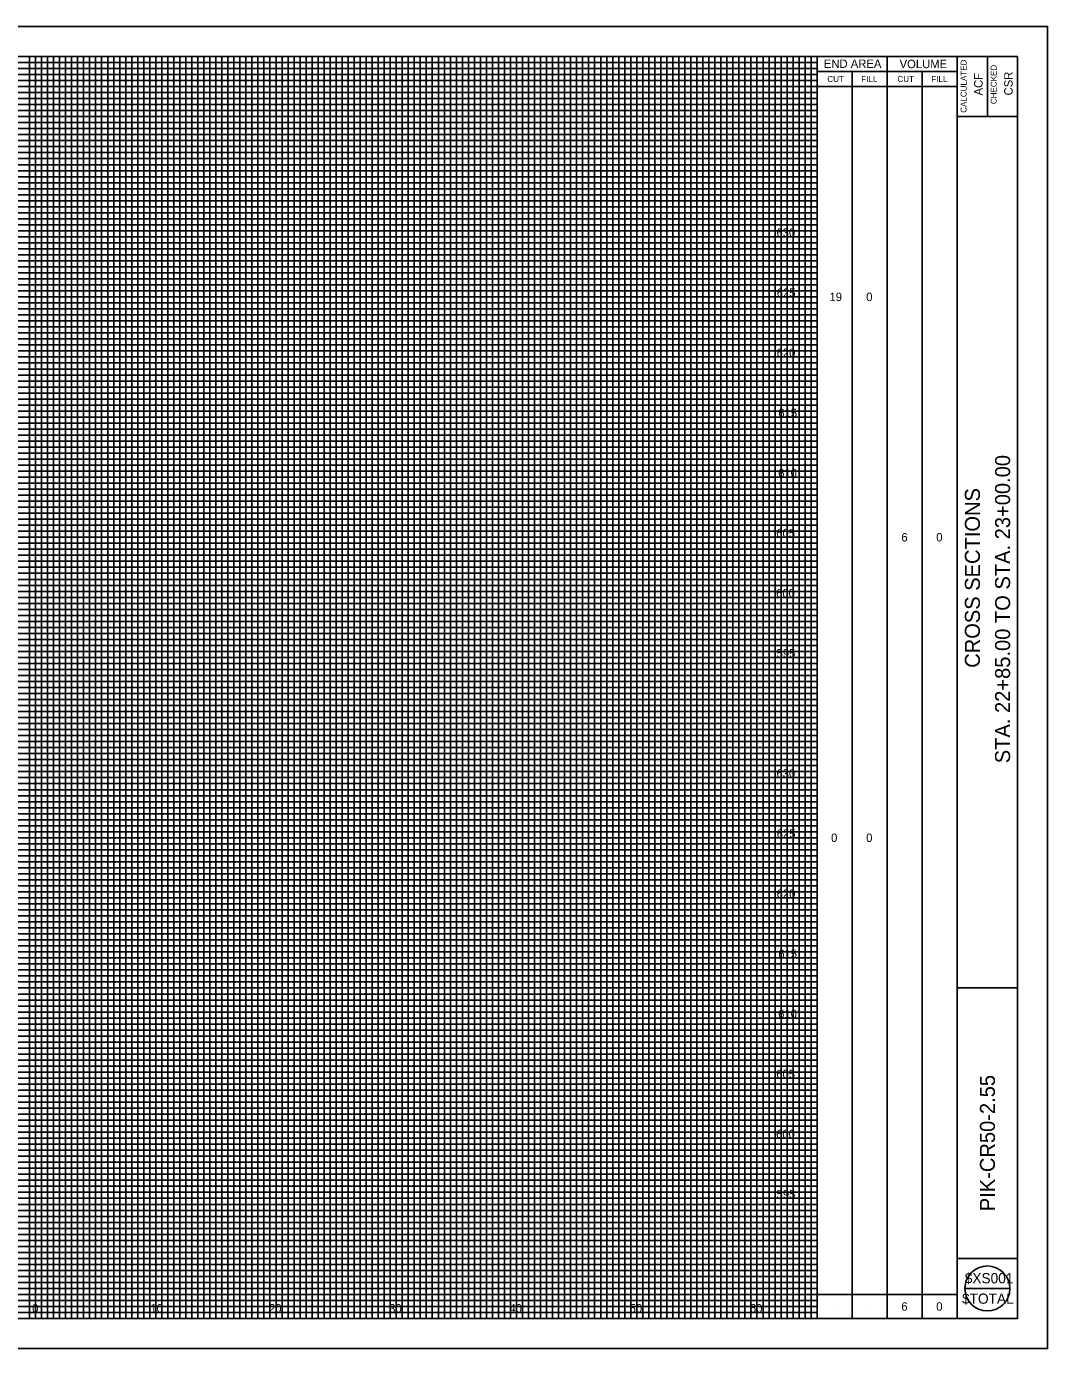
# Model space of a CAD drawing. Extents: x 1858928 to 1859278, y 421672 to 422012.
# Drawn here: x 1859012.6 to 1859097.5, y 421671.6 to 421781.6 of the extents above; entities that cross this region are included whole.
import ezdxf

# ---------------------------------------------------------------- set-up
doc = ezdxf.new("R2010")
doc.units = 0
for name, color, linetype in [('SH_Border', 7, 'Continuous'), ('SH_Cut_Line', 7, 'Continuous'), ('SH_Data', 7, 'Continuous'), ('SH_Major_Grid_Line', 7, 'Continuous'), ('SH_Minor_Grid_Line', 7, 'Continuous'), ('SH_Text', 7, 'Continuous')]:
    doc.layers.add(name, color=color, linetype=linetype)

msp = doc.modelspace()

# ---------------------------------------------------------------- linework, layer by layer
at = {"layer": 'SH_Border'}
for p, q in [((1859090.03, 421674.11), (1859090.03, 421779.11)), ((1859092.53, 421779.11), (1859092.53, 421774.11)), ((1859090.03, 421774.11), (1859095.03, 421774.11)), ((1859090.03, 421701.61), (1859095.03, 421701.61)), ((1859090.03, 421679.11), (1859095.03, 421679.11))]:
    msp.add_line(p, q, dxfattribs=at)
msp.add_lwpolyline([(1858937.53, 421779.11), (1859095.03, 421779.11), (1859095.03, 421674.11), (1858937.53, 421674.11)], close=True, dxfattribs=at)
at = {"layer": 'SH_Cut_Line'}
msp.add_lwpolyline([(1858927.53, 421671.61), (1859097.53, 421671.61), (1859097.53, 421781.61), (1858927.53, 421781.61)], close=True, dxfattribs=at)
at = {"layer": 'SH_Data'}
for p, q in [((1859078.37, 421674.11), (1859078.37, 421779.11)), ((1859084.2, 421674.11), (1859084.2, 421779.11)), ((1859078.37, 421777.86), (1859090.03, 421777.86)), ((1859081.28, 421674.11), (1859081.28, 421777.86)), ((1859087.12, 421674.11), (1859087.12, 421777.86)), ((1859078.37, 421776.61), (1859090.03, 421776.61)), ((1859090.66, 421676.61), (1859094.41, 421676.61)), ((1859078.37, 421676.11), (1859090.03, 421676.11)), ((1859079.83, 421675.11), (1859079.83, 421675.11)), ((1859082.74, 421675.11), (1859082.74, 421675.11)), ((1859085.66, 421675.11), (1859085.66, 421675.11)), ((1859088.58, 421675.11), (1859088.58, 421675.11))]:
    msp.add_line(p, q, dxfattribs=at)
msp.add_circle((1859092.53, 421676.61), 1.87, dxfattribs=at)
at = {"layer": 'SH_Major_Grid_Line'}
for p, q in [((1859013.37, 421674.11), (1859013.37, 421779.11)), ((1859018.37, 421674.11), (1859018.37, 421779.11)), ((1859023.37, 421674.11), (1859023.37, 421779.11)), ((1859028.37, 421674.11), (1859028.37, 421779.11)), ((1859033.37, 421674.11), (1859033.37, 421779.11)), ((1859038.37, 421674.11), (1859038.37, 421779.11)), ((1859043.37, 421674.11), (1859043.37, 421779.11)), ((1859048.37, 421674.11), (1859048.37, 421779.11)), ((1859053.37, 421674.11), (1859053.37, 421779.11)), ((1859058.37, 421674.11), (1859058.37, 421779.11)), ((1859063.37, 421674.11), (1859063.37, 421779.11)), ((1859068.37, 421674.11), (1859068.37, 421779.11)), ((1859073.37, 421674.11), (1859073.37, 421779.11)), ((1858943.37, 421774.11), (1859078.37, 421774.11)), ((1858943.37, 421769.11), (1859078.37, 421769.11)), ((1858943.37, 421764.11), (1859078.37, 421764.11)), ((1858943.37, 421759.11), (1859078.37, 421759.11)), ((1858943.37, 421754.11), (1859078.37, 421754.11)), ((1858943.37, 421749.11), (1859078.37, 421749.11)), ((1858943.37, 421744.11), (1859078.37, 421744.11)), ((1858943.37, 421739.11), (1859078.37, 421739.11)), ((1858943.37, 421734.11), (1859078.37, 421734.11)), ((1858943.37, 421729.11), (1859078.37, 421729.11)), ((1858943.37, 421724.11), (1859078.37, 421724.11)), ((1858943.37, 421719.11), (1859078.37, 421719.11)), ((1858943.37, 421714.11), (1859078.37, 421714.11)), ((1858943.37, 421709.11), (1859078.37, 421709.11)), ((1858943.37, 421704.11), (1859078.37, 421704.11)), ((1858943.37, 421699.11), (1859078.37, 421699.11)), ((1858943.37, 421694.11), (1859078.37, 421694.11)), ((1858943.37, 421689.11), (1859078.37, 421689.11)), ((1858943.37, 421684.11), (1859078.37, 421684.11)), ((1858943.37, 421679.11), (1859078.37, 421679.11))]:
    msp.add_line(p, q, dxfattribs=at)
at = {"layer": 'SH_Minor_Grid_Line'}
for p, q in [((1858943.37, 421778.61), (1859078.37, 421778.61)), ((1859012.87, 421674.11), (1859012.87, 421779.11)), ((1859013.87, 421674.11), (1859013.87, 421779.11)), ((1859014.37, 421674.11), (1859014.37, 421779.11)), ((1859014.87, 421674.11), (1859014.87, 421779.11)), ((1859015.37, 421674.11), (1859015.37, 421779.11)), ((1859015.87, 421674.11), (1859015.87, 421779.11)), ((1859016.37, 421674.11), (1859016.37, 421779.11)), ((1859016.87, 421674.11), (1859016.87, 421779.11)), ((1859017.37, 421674.11), (1859017.37, 421779.11)), ((1859017.87, 421674.11), (1859017.87, 421779.11)), ((1859018.87, 421674.11), (1859018.87, 421779.11)), ((1859019.37, 421674.11), (1859019.37, 421779.11)), ((1859019.87, 421674.11), (1859019.87, 421779.11)), ((1859020.37, 421674.11), (1859020.37, 421779.11)), ((1859020.87, 421674.11), (1859020.87, 421779.11)), ((1859021.37, 421674.11), (1859021.37, 421779.11)), ((1859021.87, 421674.11), (1859021.87, 421779.11)), ((1859022.37, 421674.11), (1859022.37, 421779.11)), ((1859022.87, 421674.11), (1859022.87, 421779.11)), ((1859023.87, 421674.11), (1859023.87, 421779.11)), ((1859024.37, 421674.11), (1859024.37, 421779.11)), ((1859024.87, 421674.11), (1859024.87, 421779.11)), ((1859025.37, 421674.11), (1859025.37, 421779.11)), ((1859025.87, 421674.11), (1859025.87, 421779.11)), ((1859026.37, 421674.11), (1859026.37, 421779.11)), ((1859026.87, 421674.11), (1859026.87, 421779.11)), ((1859027.37, 421674.11), (1859027.37, 421779.11)), ((1859027.87, 421674.11), (1859027.87, 421779.11)), ((1859028.87, 421674.11), (1859028.87, 421779.11)), ((1859029.37, 421674.11), (1859029.37, 421779.11)), ((1859029.87, 421674.11), (1859029.87, 421779.11)), ((1859030.37, 421674.11), (1859030.37, 421779.11)), ((1859030.87, 421674.11), (1859030.87, 421779.11)), ((1859031.37, 421674.11), (1859031.37, 421779.11)), ((1859031.87, 421674.11), (1859031.87, 421779.11)), ((1859032.37, 421674.11), (1859032.37, 421779.11)), ((1859032.87, 421674.11), (1859032.87, 421779.11)), ((1859033.87, 421674.11), (1859033.87, 421779.11)), ((1859034.37, 421674.11), (1859034.37, 421779.11)), ((1859034.87, 421674.11), (1859034.87, 421779.11)), ((1859035.37, 421674.11), (1859035.37, 421779.11)), ((1859035.87, 421674.11), (1859035.87, 421779.11)), ((1859036.37, 421674.11), (1859036.37, 421779.11)), ((1859036.87, 421674.11), (1859036.87, 421779.11)), ((1859037.37, 421674.11), (1859037.37, 421779.11)), ((1859037.87, 421674.11), (1859037.87, 421779.11)), ((1859038.87, 421674.11), (1859038.87, 421779.11)), ((1859039.37, 421674.11), (1859039.37, 421779.11)), ((1859039.87, 421674.11), (1859039.87, 421779.11)), ((1859040.37, 421674.11), (1859040.37, 421779.11)), ((1859040.87, 421674.11), (1859040.87, 421779.11)), ((1859041.37, 421674.11), (1859041.37, 421779.11)), ((1859041.87, 421674.11), (1859041.87, 421779.11)), ((1859042.37, 421674.11), (1859042.37, 421779.11)), ((1859042.87, 421674.11), (1859042.87, 421779.11)), ((1859043.87, 421674.11), (1859043.87, 421779.11)), ((1859044.37, 421674.11), (1859044.37, 421779.11)), ((1859044.87, 421674.11), (1859044.87, 421779.11)), ((1859045.37, 421674.11), (1859045.37, 421779.11)), ((1859045.87, 421674.11), (1859045.87, 421779.11)), ((1859046.37, 421674.11), (1859046.37, 421779.11)), ((1859046.87, 421674.11), (1859046.87, 421779.11)), ((1859047.37, 421674.11), (1859047.37, 421779.11)), ((1859047.87, 421674.11), (1859047.87, 421779.11)), ((1859048.87, 421674.11), (1859048.87, 421779.11)), ((1859049.37, 421674.11), (1859049.37, 421779.11)), ((1859049.87, 421674.11), (1859049.87, 421779.11)), ((1859050.37, 421674.11), (1859050.37, 421779.11)), ((1859050.87, 421674.11), (1859050.87, 421779.11)), ((1859051.37, 421674.11), (1859051.37, 421779.11)), ((1859051.87, 421674.11), (1859051.87, 421779.11)), ((1859052.37, 421674.11), (1859052.37, 421779.11)), ((1859052.87, 421674.11), (1859052.87, 421779.11)), ((1859053.87, 421674.11), (1859053.87, 421779.11)), ((1859054.37, 421674.11), (1859054.37, 421779.11)), ((1859054.87, 421674.11), (1859054.87, 421779.11)), ((1859055.37, 421674.11), (1859055.37, 421779.11)), ((1859055.87, 421674.11), (1859055.87, 421779.11)), ((1859056.37, 421674.11), (1859056.37, 421779.11)), ((1859056.87, 421674.11), (1859056.87, 421779.11)), ((1859057.37, 421674.11), (1859057.37, 421779.11)), ((1859057.87, 421674.11), (1859057.87, 421779.11)), ((1859058.87, 421674.11), (1859058.87, 421779.11)), ((1859059.37, 421674.11), (1859059.37, 421779.11)), ((1859059.87, 421674.11), (1859059.87, 421779.11)), ((1859060.37, 421674.11), (1859060.37, 421779.11)), ((1859060.87, 421674.11), (1859060.87, 421779.11)), ((1859061.37, 421674.11), (1859061.37, 421779.11)), ((1859061.87, 421674.11), (1859061.87, 421779.11)), ((1859062.37, 421674.11), (1859062.37, 421779.11)), ((1859062.87, 421674.11), (1859062.87, 421779.11)), ((1859063.87, 421674.11), (1859063.87, 421779.11)), ((1859064.37, 421674.11), (1859064.37, 421779.11)), ((1859064.87, 421674.11), (1859064.87, 421779.11)), ((1859065.37, 421674.11), (1859065.37, 421779.11)), ((1859065.87, 421674.11), (1859065.87, 421779.11)), ((1859066.37, 421674.11), (1859066.37, 421779.11)), ((1859066.87, 421674.11), (1859066.87, 421779.11)), ((1859067.37, 421674.11), (1859067.37, 421779.11)), ((1859067.87, 421674.11), (1859067.87, 421779.11)), ((1859068.87, 421674.11), (1859068.87, 421779.11)), ((1859069.37, 421674.11), (1859069.37, 421779.11)), ((1859069.87, 421674.11), (1859069.87, 421779.11)), ((1859070.37, 421674.11), (1859070.37, 421779.11)), ((1859070.87, 421674.11), (1859070.87, 421779.11)), ((1859071.37, 421674.11), (1859071.37, 421779.11)), ((1859071.87, 421674.11), (1859071.87, 421779.11)), ((1859072.37, 421674.11), (1859072.37, 421779.11)), ((1859072.87, 421674.11), (1859072.87, 421779.11)), ((1859073.87, 421674.11), (1859073.87, 421779.11)), ((1859074.37, 421674.11), (1859074.37, 421779.11)), ((1859074.87, 421674.11), (1859074.87, 421779.11)), ((1859075.37, 421674.11), (1859075.37, 421779.11)), ((1859075.87, 421674.11), (1859075.87, 421779.11)), ((1859076.37, 421674.11), (1859076.37, 421779.11)), ((1859076.87, 421674.11), (1859076.87, 421779.11)), ((1859077.37, 421674.11), (1859077.37, 421779.11)), ((1859077.87, 421674.11), (1859077.87, 421779.11)), ((1858943.37, 421778.11), (1859078.37, 421778.11)), ((1858943.37, 421777.61), (1859078.37, 421777.61)), ((1858943.37, 421777.11), (1859078.37, 421777.11)), ((1858943.37, 421776.61), (1859078.37, 421776.61)), ((1858943.37, 421776.11), (1859078.37, 421776.11)), ((1858943.37, 421775.61), (1859078.37, 421775.61)), ((1858943.37, 421775.11), (1859078.37, 421775.11)), ((1858943.37, 421774.61), (1859078.37, 421774.61)), ((1858943.37, 421773.61), (1859078.37, 421773.61)), ((1858943.37, 421773.11), (1859078.37, 421773.11)), ((1858943.37, 421772.61), (1859078.37, 421772.61)), ((1858943.37, 421772.11), (1859078.37, 421772.11)), ((1858943.37, 421771.61), (1859078.37, 421771.61)), ((1858943.37, 421771.11), (1859078.37, 421771.11)), ((1858943.37, 421770.61), (1859078.37, 421770.61)), ((1858943.37, 421770.11), (1859078.37, 421770.11)), ((1858943.37, 421769.61), (1859078.37, 421769.61)), ((1858943.37, 421768.61), (1859078.37, 421768.61)), ((1858943.37, 421768.11), (1859078.37, 421768.11)), ((1858943.37, 421767.61), (1859078.37, 421767.61)), ((1858943.37, 421767.11), (1859078.37, 421767.11)), ((1858943.37, 421766.61), (1859078.37, 421766.61)), ((1858943.37, 421766.11), (1859078.37, 421766.11)), ((1858943.37, 421765.61), (1859078.37, 421765.61)), ((1858943.37, 421765.11), (1859078.37, 421765.11)), ((1858943.37, 421764.61), (1859078.37, 421764.61)), ((1858943.37, 421763.61), (1859078.37, 421763.61)), ((1858943.37, 421763.11), (1859078.37, 421763.11)), ((1858943.37, 421762.61), (1859078.37, 421762.61)), ((1858943.37, 421762.11), (1859078.37, 421762.11)), ((1858943.37, 421761.61), (1859078.37, 421761.61)), ((1858943.37, 421761.11), (1859078.37, 421761.11)), ((1858943.37, 421760.61), (1859078.37, 421760.61)), ((1858943.37, 421760.11), (1859078.37, 421760.11)), ((1858943.37, 421759.61), (1859078.37, 421759.61)), ((1858943.37, 421758.61), (1859078.37, 421758.61)), ((1858943.37, 421758.11), (1859078.37, 421758.11)), ((1858943.37, 421757.61), (1859078.37, 421757.61)), ((1858943.37, 421757.11), (1859078.37, 421757.11)), ((1858943.37, 421756.61), (1859078.37, 421756.61)), ((1858943.37, 421756.11), (1859078.37, 421756.11)), ((1858943.37, 421755.61), (1859078.37, 421755.61)), ((1858943.37, 421755.11), (1859078.37, 421755.11)), ((1858943.37, 421754.61), (1859078.37, 421754.61)), ((1858943.37, 421753.61), (1859078.37, 421753.61)), ((1858943.37, 421753.11), (1859078.37, 421753.11)), ((1858943.37, 421752.61), (1859078.37, 421752.61)), ((1858943.37, 421752.11), (1859078.37, 421752.11)), ((1858943.37, 421751.61), (1859078.37, 421751.61)), ((1858943.37, 421751.11), (1859078.37, 421751.11)), ((1858943.37, 421750.61), (1859078.37, 421750.61)), ((1858943.37, 421750.11), (1859078.37, 421750.11)), ((1858943.37, 421749.61), (1859078.37, 421749.61)), ((1858943.37, 421748.61), (1859078.37, 421748.61)), ((1858943.37, 421748.11), (1859078.37, 421748.11)), ((1858943.37, 421747.61), (1859078.37, 421747.61)), ((1858943.37, 421747.11), (1859078.37, 421747.11)), ((1858943.37, 421746.61), (1859078.37, 421746.61)), ((1858943.37, 421746.11), (1859078.37, 421746.11)), ((1858943.37, 421745.61), (1859078.37, 421745.61)), ((1858943.37, 421745.11), (1859078.37, 421745.11)), ((1858943.37, 421744.61), (1859078.37, 421744.61)), ((1858943.37, 421743.61), (1859078.37, 421743.61)), ((1858943.37, 421743.11), (1859078.37, 421743.11)), ((1858943.37, 421742.61), (1859078.37, 421742.61)), ((1858943.37, 421742.11), (1859078.37, 421742.11)), ((1858943.37, 421741.61), (1859078.37, 421741.61)), ((1858943.37, 421741.11), (1859078.37, 421741.11)), ((1858943.37, 421740.61), (1859078.37, 421740.61)), ((1858943.37, 421740.11), (1859078.37, 421740.11)), ((1858943.37, 421739.61), (1859078.37, 421739.61)), ((1858943.37, 421738.61), (1859078.37, 421738.61)), ((1858943.37, 421738.11), (1859078.37, 421738.11)), ((1858943.37, 421737.61), (1859078.37, 421737.61)), ((1858943.37, 421737.11), (1859078.37, 421737.11)), ((1858943.37, 421736.61), (1859078.37, 421736.61)), ((1858943.37, 421736.11), (1859078.37, 421736.11)), ((1858943.37, 421735.61), (1859078.37, 421735.61)), ((1858943.37, 421735.11), (1859078.37, 421735.11)), ((1858943.37, 421734.61), (1859078.37, 421734.61)), ((1858943.37, 421733.61), (1859078.37, 421733.61)), ((1858943.37, 421733.11), (1859078.37, 421733.11)), ((1858943.37, 421732.61), (1859078.37, 421732.61)), ((1858943.37, 421732.11), (1859078.37, 421732.11)), ((1858943.37, 421731.61), (1859078.37, 421731.61)), ((1858943.37, 421731.11), (1859078.37, 421731.11)), ((1858943.37, 421730.61), (1859078.37, 421730.61)), ((1858943.37, 421730.11), (1859078.37, 421730.11)), ((1858943.37, 421729.61), (1859078.37, 421729.61)), ((1858943.37, 421728.61), (1859078.37, 421728.61)), ((1858943.37, 421728.11), (1859078.37, 421728.11)), ((1858943.37, 421727.61), (1859078.37, 421727.61)), ((1858943.37, 421727.11), (1859078.37, 421727.11)), ((1858943.37, 421726.61), (1859078.37, 421726.61)), ((1858943.37, 421726.11), (1859078.37, 421726.11)), ((1858943.37, 421725.61), (1859078.37, 421725.61)), ((1858943.37, 421725.11), (1859078.37, 421725.11)), ((1858943.37, 421724.61), (1859078.37, 421724.61)), ((1858943.37, 421723.61), (1859078.37, 421723.61)), ((1858943.37, 421723.11), (1859078.37, 421723.11)), ((1858943.37, 421722.61), (1859078.37, 421722.61)), ((1858943.37, 421722.11), (1859078.37, 421722.11)), ((1858943.37, 421721.61), (1859078.37, 421721.61)), ((1858943.37, 421721.11), (1859078.37, 421721.11)), ((1858943.37, 421720.61), (1859078.37, 421720.61)), ((1858943.37, 421720.11), (1859078.37, 421720.11)), ((1858943.37, 421719.61), (1859078.37, 421719.61)), ((1858943.37, 421718.61), (1859078.37, 421718.61)), ((1858943.37, 421718.11), (1859078.37, 421718.11)), ((1858943.37, 421717.61), (1859078.37, 421717.61)), ((1858943.37, 421717.11), (1859078.37, 421717.11)), ((1858943.37, 421716.61), (1859078.37, 421716.61)), ((1858943.37, 421716.11), (1859078.37, 421716.11)), ((1858943.37, 421715.61), (1859078.37, 421715.61)), ((1858943.37, 421715.11), (1859078.37, 421715.11)), ((1858943.37, 421714.61), (1859078.37, 421714.61)), ((1858943.37, 421713.61), (1859078.37, 421713.61)), ((1858943.37, 421713.11), (1859078.37, 421713.11)), ((1858943.37, 421712.61), (1859078.37, 421712.61)), ((1858943.37, 421712.11), (1859078.37, 421712.11)), ((1858943.37, 421711.61), (1859078.37, 421711.61)), ((1858943.37, 421711.11), (1859078.37, 421711.11)), ((1858943.37, 421710.61), (1859078.37, 421710.61)), ((1858943.37, 421710.11), (1859078.37, 421710.11)), ((1858943.37, 421709.61), (1859078.37, 421709.61)), ((1858943.37, 421708.61), (1859078.37, 421708.61)), ((1858943.37, 421708.11), (1859078.37, 421708.11)), ((1858943.37, 421707.61), (1859078.37, 421707.61)), ((1858943.37, 421707.11), (1859078.37, 421707.11)), ((1858943.37, 421706.61), (1859078.37, 421706.61)), ((1858943.37, 421706.11), (1859078.37, 421706.11)), ((1858943.37, 421705.61), (1859078.37, 421705.61)), ((1858943.37, 421705.11), (1859078.37, 421705.11)), ((1858943.37, 421704.61), (1859078.37, 421704.61)), ((1858943.37, 421703.61), (1859078.37, 421703.61)), ((1858943.37, 421703.11), (1859078.37, 421703.11)), ((1858943.37, 421702.61), (1859078.37, 421702.61)), ((1858943.37, 421702.11), (1859078.37, 421702.11)), ((1858943.37, 421701.61), (1859078.37, 421701.61)), ((1858943.37, 421701.11), (1859078.37, 421701.11)), ((1858943.37, 421700.61), (1859078.37, 421700.61)), ((1858943.37, 421700.11), (1859078.37, 421700.11)), ((1858943.37, 421699.61), (1859078.37, 421699.61)), ((1858943.37, 421698.61), (1859078.37, 421698.61)), ((1858943.37, 421698.11), (1859078.37, 421698.11)), ((1858943.37, 421697.61), (1859078.37, 421697.61)), ((1858943.37, 421697.11), (1859078.37, 421697.11)), ((1858943.37, 421696.61), (1859078.37, 421696.61)), ((1858943.37, 421696.11), (1859078.37, 421696.11)), ((1858943.37, 421695.61), (1859078.37, 421695.61)), ((1858943.37, 421695.11), (1859078.37, 421695.11)), ((1858943.37, 421694.61), (1859078.37, 421694.61)), ((1858943.37, 421693.61), (1859078.37, 421693.61)), ((1858943.37, 421693.11), (1859078.37, 421693.11)), ((1858943.37, 421692.61), (1859078.37, 421692.61)), ((1858943.37, 421692.11), (1859078.37, 421692.11)), ((1858943.37, 421691.61), (1859078.37, 421691.61)), ((1858943.37, 421691.11), (1859078.37, 421691.11)), ((1858943.37, 421690.61), (1859078.37, 421690.61)), ((1858943.37, 421690.11), (1859078.37, 421690.11)), ((1858943.37, 421689.61), (1859078.37, 421689.61)), ((1858943.37, 421688.61), (1859078.37, 421688.61)), ((1858943.37, 421688.11), (1859078.37, 421688.11)), ((1858943.37, 421687.61), (1859078.37, 421687.61)), ((1858943.37, 421687.11), (1859078.37, 421687.11)), ((1858943.37, 421686.61), (1859078.37, 421686.61)), ((1858943.37, 421686.11), (1859078.37, 421686.11)), ((1858943.37, 421685.61), (1859078.37, 421685.61)), ((1858943.37, 421685.11), (1859078.37, 421685.11)), ((1858943.37, 421684.61), (1859078.37, 421684.61)), ((1858943.37, 421683.61), (1859078.37, 421683.61)), ((1858943.37, 421683.11), (1859078.37, 421683.11)), ((1858943.37, 421682.61), (1859078.37, 421682.61)), ((1858943.37, 421682.11), (1859078.37, 421682.11)), ((1858943.37, 421681.61), (1859078.37, 421681.61)), ((1858943.37, 421681.11), (1859078.37, 421681.11)), ((1858943.37, 421680.61), (1859078.37, 421680.61)), ((1858943.37, 421680.11), (1859078.37, 421680.11)), ((1858943.37, 421679.61), (1859078.37, 421679.61)), ((1858943.37, 421678.61), (1859078.37, 421678.61)), ((1858943.37, 421678.11), (1859078.37, 421678.11)), ((1858943.37, 421677.61), (1859078.37, 421677.61)), ((1858943.37, 421677.11), (1859078.37, 421677.11)), ((1858943.37, 421676.61), (1859078.37, 421676.61)), ((1858943.37, 421676.11), (1859078.37, 421676.11)), ((1858943.37, 421675.61), (1859078.37, 421675.61)), ((1858943.37, 421675.11), (1859078.37, 421675.11)), ((1858943.37, 421674.61), (1859078.37, 421674.61))]:
    msp.add_line(p, q, dxfattribs=at)

# ---------------------------------------------------------------- texts
at = {"layer": 'SH_Data'}
for s, height, p in [('END AREA', 0.7, (1859078.93, 421778.16)), ('VOLUME', 0.7, (1859085.23, 421778.14)), ('CUT', 0.5, (1859079.22, 421776.99)), ('FILL', 0.5, (1859082.04, 421776.99)), ('CUT', 0.5, (1859085.05, 421776.99)), ('FILL', 0.5, (1859087.87, 421776.99)), ('$XS001', 0.85, (1859090.65, 421677.04)), ('$TOTAL', 0.85, (1859090.42, 421675.34))]:
    msp.add_text(s, height=height, dxfattribs=at).set_placement(p)
for s, height, p in [('CALCULATED', 0.5, (1859090.8, 421774.43)), ('ACF', 0.7, (1859092.13, 421775.87)), ('CHECKED', 0.5, (1859093.3, 421775.15)), ('CSR', 0.7, (1859094.63, 421775.87)), ('STA. 22+85.00 TO STA. 23+00.00', 1.25, (1859094.42, 421720.31)), ('CROSS SECTIONS', 1.25, (1859091.91, 421728.25)), ('PIK-CR50-2.55', 1.25, (1859093.16, 421683.04))]:
    msp.add_text(s, height=height, rotation=90, dxfattribs=at).set_placement(p)
at = {"layer": 'SH_Text'}
for s, p in [('630', (1859074.99, 421764.11)), ('625', (1859075.01, 421759.11)), ('19', (1859079.4, 421758.76)), ('0', (1859082.45, 421758.76)), ('620', (1859075, 421754.11)), ('615', (1859075.14, 421749.11)), ('610', (1859075.13, 421744.11)), ('605', (1859074.97, 421739.11)), ('6', (1859085.38, 421738.76)), ('0', (1859088.28, 421738.76)), ('600', (1859074.96, 421734.11)), ('595', (1859075, 421729.11)), ('630', (1859074.99, 421719.11)), ('625', (1859075.01, 421714.11)), ('0', (1859079.53, 421713.76)), ('0', (1859082.45, 421713.76)), ('620', (1859075, 421709.11)), ('615', (1859075.14, 421704.11)), ('610', (1859075.13, 421699.11)), ('605', (1859074.97, 421694.11)), ('600', (1859074.96, 421689.11)), ('595', (1859075, 421684.11)), ('0', (1859013.09, 421674.61)), ('0', (1859013.09, 421674.61)), ('10', (1859022.92, 421674.61)), ('20', (1859032.79, 421674.61)), ('30', (1859042.78, 421674.61)), ('40', (1859052.78, 421674.61)), ('50', (1859062.78, 421674.61)), ('60', (1859072.78, 421674.61)), ('6', (1859085.38, 421674.76)), ('0', (1859088.28, 421674.76))]:
    msp.add_text(s, height=0.7, dxfattribs=at).set_placement(p)

doc.saveas('drawing.dxf')
